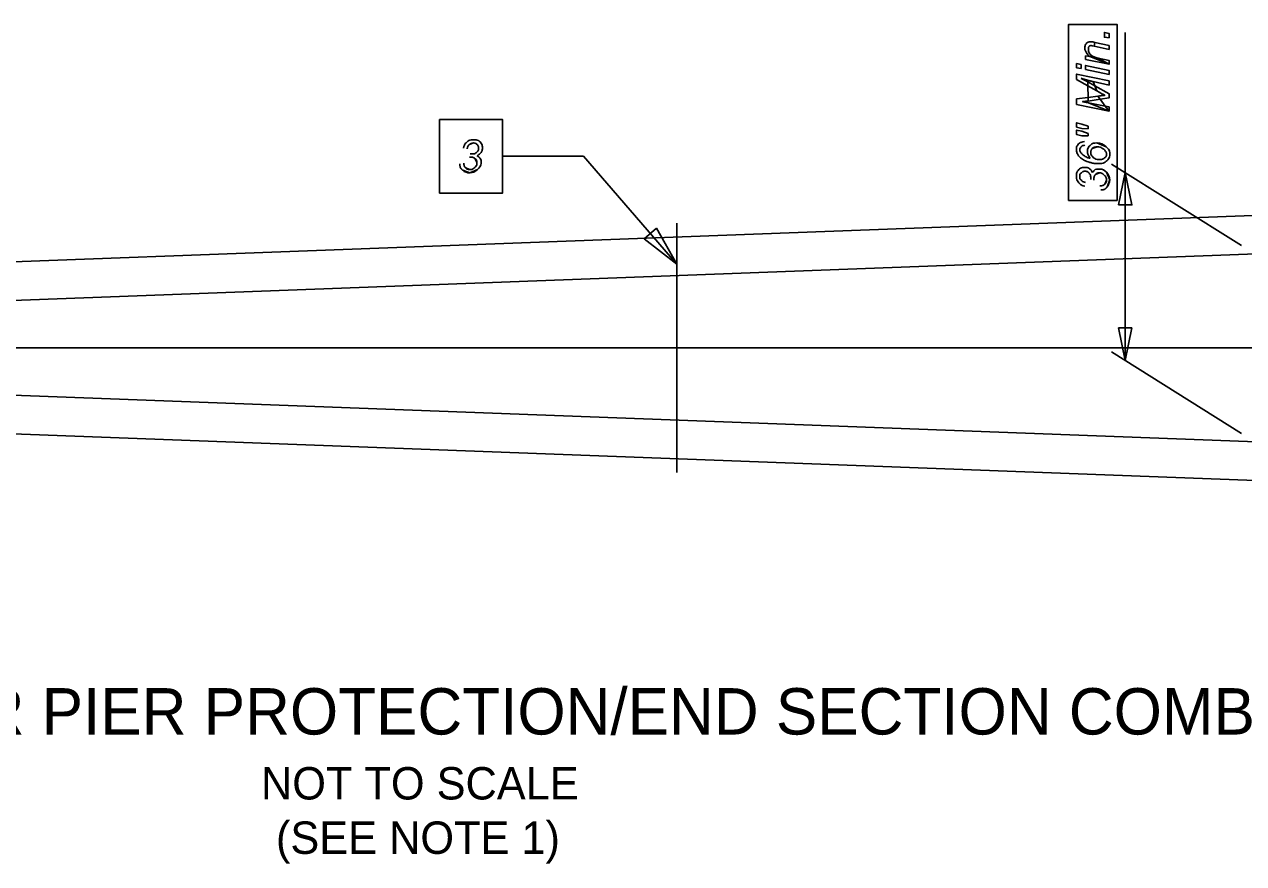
# Model space of a CAD drawing. Extents: x 0 to 680, y 0 to 440.
# Drawn here: x 297.5 to 402.6, y 321.3 to 393.7 of the extents above; entities that cross this region are included whole.
import ezdxf

# ---------------------------------------------------------------- set-up
doc = ezdxf.new("R2010")
doc.units = 0
doc.layers.add('Default', color=7, linetype='Continuous')

msp = doc.modelspace()

# ---------------------------------------------------------------- linework, layer by layer
at = {"layer": 'Default'}
for p, q in [((392.42, 392.97), (392.42, 380.89)), ((335.89, 383.3), (336.22, 383.44)), ((389.59, 382.97), (390, 383.11)), ((389.98, 383.44), (390.78, 383.11)), ((336.39, 382.08), (336.53, 381.75)), ((336.55, 382.33), (336.8, 382.11)), ((338.74, 382.3), (345.72, 382.3)), ((353.76, 372.99), (345.72, 382.3)), ((402.45, 374.6), (391.25, 381.61)), ((335.92, 380.86), (335.31, 381.08)), ((335.89, 381.14), (335.56, 381.28)), ((336.58, 381.14), (335.92, 380.86)), ((389.62, 380.89), (389.84, 381.14)), ((389.87, 380.72), (390.2, 380.86)), ((390.81, 380.92), (391.09, 380.25)), ((392.42, 380.89), (392.42, 364.68)), ((390.81, 380.22), (390.67, 379.89)), ((391.09, 380.25), (390.86, 379.64)), ((353.76, 355.01), (353.76, 376.51)), ((402.45, 358.39), (391.25, 365.43))]:
    msp.add_line(p, q, dxfattribs=at)
for points in [[(391.72, 378.48), (391.72, 393.66), (387.54, 393.66), (387.54, 378.48)], [(391.03, 392.5), (391.03, 392.89), (390.64, 392.97), (390.64, 392.55)], [(389.76, 391.78), (391.03, 391.5), (391.03, 391.83), (389.81, 392.11)], [(388.62, 389.87), (388.62, 390.2), (388.23, 390.28), (388.23, 389.92)], [(389.37, 390.89), (389.01, 390.95), (389.01, 390.64), (391.03, 390.23)], [(391.03, 389.34), (391.03, 389.7), (389.01, 390.12), (389.01, 389.78)], [(391.03, 390.23), (391.03, 390.56), (390.09, 390.75)], [(390.27, 387.2), (391.03, 387.32), (391.03, 387.68), (389.81, 388.36), (389.98, 387.93), (389.21, 388.37), (389.22, 387.37), (390.06, 387.48)], [(390.27, 387.2), (389.23, 387.04), (389.22, 387.37), (388.23, 387.23), (388.23, 386.76), (391.03, 386.18), (389.26, 386.9), (390.71, 386.61)], [(391.03, 386.18), (391.03, 386.54), (390.71, 386.61)], [(333.31, 379.12), (338.74, 379.12), (338.74, 385.46), (333.31, 385.46)], [(389.23, 384.66), (389.23, 384.88), (388.7, 385.07), (388.23, 385.18), (388.23, 384.8), (388.7, 384.69)], [(389.23, 384.05), (389.23, 384.24), (388.7, 384.44), (388.23, 384.55), (388.23, 384.16), (388.7, 384.05)], [(391.86, 378.09), (392.42, 380.89), (393, 378.09)], [(352.01, 376.1), (353.76, 372.99), (350.96, 375.18)], [(393, 367.48), (392.42, 364.68), (391.86, 367.48)]]:
    msp.add_lwpolyline(points, close=True, dxfattribs=at)
for points in [[(389.2, 388.7), (389.81, 388.36), (389.67, 388.73), (391.03, 388.43), (391.03, 388.79), (388.23, 389.37), (388.23, 388.92), (389.21, 388.37), (389.2, 388.7), (388.62, 389.01)], [(174.23, 371.99), (287.28, 372.83), (453.43, 379.06)], [(287.28, 369.5), (453.52, 375.73), (573.19, 375.73)], [(104.43, 365.76), (254.03, 365.76), (634.24, 365.76)], [(287.28, 362.02), (453.52, 355.78), (573.19, 355.78)], [(174.23, 359.52), (287.28, 358.69), (453.43, 352.46)]]:
    msp.add_lwpolyline(points, dxfattribs=at)
for centre, radius, start, end in [((383.21, 377.98), 12.29, 60.8221, 63.886), ((336.22, 382.98), 0.459, 89.5095, 135.7302), ((390, 382.43), 0.681, 89.6598, 127.2101), ((389.99, 382.33), 1.11, 44.4526, 90.5885), ((336.07, 381.75), 0.459, 359.5095, 45.7302), ((336.26, 381.75), 0.654, 33.5919, 63.141), ((335.9, 381.77), 0.913, 229.2075, 270.8263), ((335.88, 381.6), 0.459, 224.2698, 270.4905), ((335.92, 381.78), 0.918, 269.5095, 315.7302), ((390.2, 380.59), 0.654, 123.5919, 153.141), ((390.19, 380.4), 0.459, 89.5095, 135.7302), ((390.12, 380.24), 0.968, 0.7634, 44.4763), ((390.35, 380.22), 0.459, 314.2698, 0.4905), ((390.17, 380.24), 0.913, 319.2075, 0.8263)]:
    msp.add_arc(centre, radius, start, end, dxfattribs=at)
for points, degree in [([(389.81, 392.11), (389.64, 392.14), (389.53, 392.17), (389.45, 392.17), (389.31, 392.17), (389.17, 392.11), (389.09, 392.03), (389.01, 391.95), (388.95, 391.81), (388.95, 391.64), (388.95, 391.5), (388.98, 391.39), (389.06, 391.28), (389.12, 391.14), (389.23, 391.03), (389.37, 390.89)], 3), ([(390.09, 390.75), (389.78, 390.84), (389.56, 390.92), (389.42, 391.06), (389.31, 391.2), (389.26, 391.36), (389.26, 391.56), (389.26, 391.64), (389.26, 391.7), (389.31, 391.75), (389.34, 391.81), (389.4, 391.83), (389.48, 391.83), (389.53, 391.83), (389.62, 391.81), (389.76, 391.78)], 3), ([(388.62, 389.01), (389.01, 388.9), (389.37, 388.79), (389.67, 388.73)], 2), ([(389.98, 387.93), (390.28, 387.76), (390.53, 387.62), (390.73, 387.54), (390.5, 387.54), (390.28, 387.51), (390.06, 387.48)], 3), ([(389.26, 386.9), (389.12, 386.93), (388.92, 386.96), (388.67, 387.01), (388.9, 387.01), (389.06, 387.04), (389.23, 387.04)], 3), ([(336.55, 382.33), (336.69, 382.41), (336.8, 382.5), (336.89, 382.61), (336.97, 382.72), (337, 382.86), (337, 382.99), (337, 383.19), (336.94, 383.38), (336.8, 383.52), (336.66, 383.66), (336.47, 383.72), (336.25, 383.72), (336.03, 383.72), (335.83, 383.66), (335.67, 383.52), (335.53, 383.41), (335.42, 383.22), (335.36, 382.99)], 3), ([(335.69, 382.94), (335.72, 383.08), (335.78, 383.22), (335.89, 383.3)], 2), ([(336.22, 383.44), (336.33, 383.44), (336.44, 383.41), (336.53, 383.3), (336.64, 383.22), (336.66, 383.11), (336.66, 382.99), (336.66, 382.86), (336.61, 382.72), (336.5, 382.63), (336.39, 382.52), (336.25, 382.5), (336.05, 382.5), (336.03, 382.5), (336, 382.5), (335.94, 382.5)], 3), ([(388.92, 383.55), (388.7, 383.52), (388.54, 383.47), (388.4, 383.36), (388.29, 383.22), (388.23, 383.08), (388.23, 382.88), (388.23, 382.72), (388.26, 382.58), (388.34, 382.44), (388.4, 382.33), (388.51, 382.22), (388.65, 382.08), (388.81, 381.97), (389.01, 381.89), (389.23, 381.8), (389.53, 381.72), (389.81, 381.66), (390.09, 381.66), (390.42, 381.66), (390.64, 381.75), (390.84, 381.89), (391, 382.05), (391.09, 382.25), (391.09, 382.47), (391.09, 382.72), (390.97, 382.94), (390.78, 383.11)], 3), ([(389.98, 383.44), (389.73, 383.44), (389.53, 383.36), (389.4, 383.22), (389.26, 383.08), (389.17, 382.91), (389.17, 382.69), (389.17, 382.61), (389.2, 382.5), (389.23, 382.41), (389.28, 382.3), (389.34, 382.22), (389.42, 382.11), (389.28, 382.14), (389.15, 382.19), (388.98, 382.27), (388.84, 382.36), (388.73, 382.44), (388.65, 382.55), (388.56, 382.63), (388.51, 382.75), (388.51, 382.86), (388.51, 382.94), (388.56, 383.02), (388.62, 383.11), (388.67, 383.16), (388.79, 383.22), (388.95, 383.24)], 3), ([(390, 383.11), (390.14, 383.11), (390.28, 383.08), (390.42, 382.99), (390.53, 382.94), (390.64, 382.86), (390.7, 382.75), (390.78, 382.66), (390.81, 382.58), (390.81, 382.47), (390.81, 382.36), (390.75, 382.25), (390.64, 382.14), (390.53, 382.05), (390.39, 382), (390.25, 382), (390, 382), (389.81, 382.08), (389.67, 382.19), (389.53, 382.33), (389.45, 382.47), (389.45, 382.63), (389.45, 382.75), (389.51, 382.86), (389.59, 382.97)], 3), ([(335.06, 381.64), (335.06, 381.42), (335.14, 381.22), (335.31, 381.08)], 2), ([(335.56, 381.28), (335.47, 381.36), (335.42, 381.5), (335.39, 381.69)], 2), ([(335.89, 382.22), (335.94, 382.22), (336, 382.22), (336, 382.22), (336.16, 382.22), (336.28, 382.16), (336.39, 382.08)], 3), ([(336.53, 381.75), (336.53, 381.58), (336.47, 381.44), (336.33, 381.33), (336.22, 381.19), (336.05, 381.14), (335.89, 381.14)], 3), ([(336.58, 381.14), (336.77, 381.33), (336.89, 381.55), (336.89, 381.8), (336.89, 381.91), (336.86, 382.03), (336.8, 382.11)], 3), ([(389.62, 380.89), (389.53, 381.03), (389.45, 381.14), (389.34, 381.22), (389.23, 381.3), (389.09, 381.33), (388.95, 381.33), (388.73, 381.33), (388.56, 381.28), (388.43, 381.14), (388.29, 381), (388.23, 380.81), (388.23, 380.58), (388.23, 380.36), (388.29, 380.17), (388.43, 380), (388.54, 379.86), (388.73, 379.75), (388.95, 379.7)], 3), ([(389.01, 380.03), (388.84, 380.06), (388.73, 380.11), (388.65, 380.22), (388.54, 380.31), (388.51, 380.42), (388.51, 380.56), (388.51, 380.67), (388.54, 380.78), (388.65, 380.86), (388.73, 380.94), (388.84, 381), (388.95, 381), (389.09, 381), (389.23, 380.94), (389.31, 380.83), (389.4, 380.72), (389.45, 380.58), (389.45, 380.39), (389.45, 380.36), (389.45, 380.33), (389.45, 380.28)], 3), ([(389.73, 380.22), (389.73, 380.28), (389.73, 380.33), (389.73, 380.33), (389.73, 380.5), (389.78, 380.61), (389.87, 380.72)], 3), ([(390.81, 380.92), (390.61, 381.11), (390.39, 381.19), (390.14, 381.19), (390.03, 381.19), (389.92, 381.17), (389.84, 381.14)], 3), ([(390.2, 380.86), (390.37, 380.86), (390.5, 380.78), (390.61, 380.67), (390.75, 380.56), (390.81, 380.39), (390.81, 380.22)], 3), ([(390.67, 379.89), (390.59, 379.81), (390.45, 379.75), (390.25, 379.73)], 2), ([(390.31, 379.39), (390.53, 379.39), (390.73, 379.48), (390.86, 379.64)], 2)]:
    msp.add_open_spline(points, degree=degree, dxfattribs=at)

# ---------------------------------------------------------------- texts
for s, height, p in [('MEDIAN BARRIER PIER PROTECTION/END SECTION COMBINED DETAIL', 4, (251.45, 332.42)), ('NOT TO SCALE', 2.7931, (317.91, 326.82)), ('(SEE NOTE 1)', 2.7931, (319.2, 322.13))]:
    msp.add_text(s, height=height, dxfattribs=at).set_placement(p)

doc.saveas('drawing.dxf')
